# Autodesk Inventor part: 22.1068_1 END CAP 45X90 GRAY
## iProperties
Created: 2007-01
Part Number: 22.1068_1 END CAP 45X90 GRAY
Document SubType Name: Modeling
Designer: Andy Moles
Material: ABS Plastic
Density: 1.06 g/cm^3
Mass: 12.7399 g
Surface Area: 87.2921 cm^2
Volume: 12.0188 cm^3
Author: Andy Moles
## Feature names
1. Extrusion1
2. Fillet1
3. Fillet2
4. Extrusion2
5. Fillet3
6. Mirror1
7. Mirror2
